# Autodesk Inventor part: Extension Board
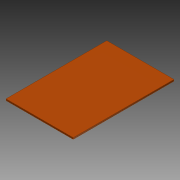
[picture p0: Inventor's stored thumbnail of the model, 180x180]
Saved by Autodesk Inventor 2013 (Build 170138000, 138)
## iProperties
Created: 2012-10
Part Number: Extension Board
Material: Phenolharz
Document SubType Name: Modeling
Designer: rYan
Mass: 16.2288 g
Surface Area: 152.6 cm^2
Volume: 11.76 cm^3
Density: 1.38 g/cm^3
Author: rYan
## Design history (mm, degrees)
sketch "Skizze1"
  geometry: L1 (-35, 52.5)-(35, 52.5); L2 (35, 52.5)-(35, -52.5); L3 (35, -52.5)-(-35, -52.5); L4 (-35, -52.5)-(-35, 52.5); L5 (0, 73.5)-(0, -73.5) reference; L6 (-49, 0)-(49, 0) reference; 1 further point
  constraints: 8 end point, 2 parallel, 1 horizontal, 1 perpendicular, 2 other
  dimensions: "d0" = 70 distance of L2.end L3.end; "d1" = 105 distance of L1.end L2.end
extrude "Extrusion1" new body sketch "Skizze1" distance "d2" = 1.6; taper "d3" = 0 deg
node "Volumenkörper1"
